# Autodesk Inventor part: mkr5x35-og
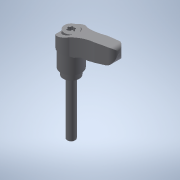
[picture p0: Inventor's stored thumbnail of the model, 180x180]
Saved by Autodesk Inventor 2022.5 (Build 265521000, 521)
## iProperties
Created: 2017-09
Part Number: mkr5x35-og
Material: 一般
Document SubType Name: Modeling
Designer: imaocorp
Density: 1 g/cm^3
Appearance: 既定
Author: imaocorp
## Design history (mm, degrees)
node "mkr5x35-og.x_t1"
node "mkr5x35-og"
node "Base1"
